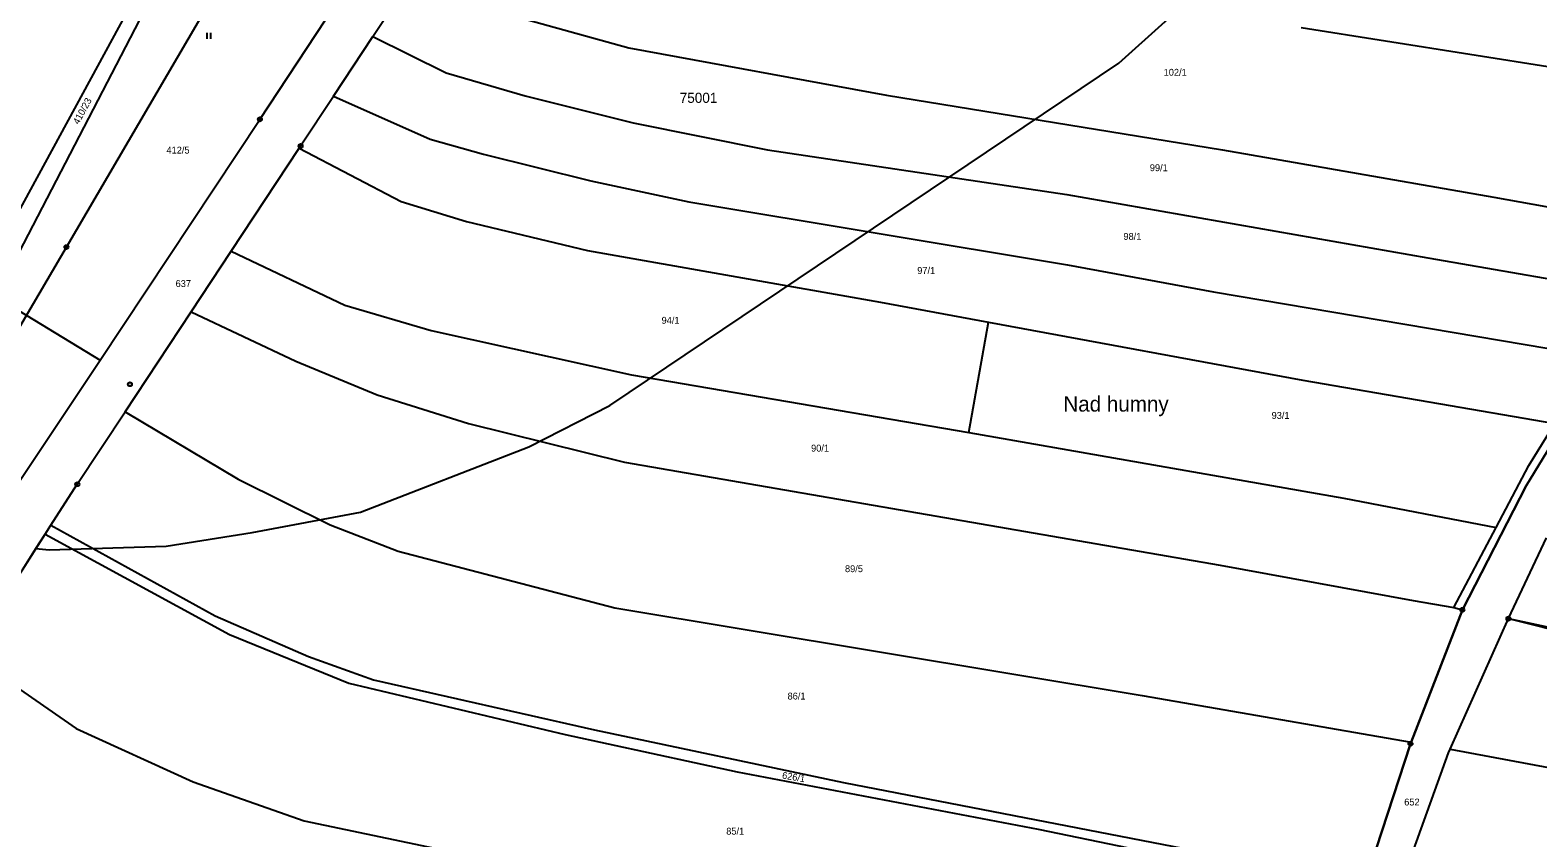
# Model space of a CAD drawing. Extents: x -743888 to -742027, y -1128394 to -1126768.
# Drawn here: x -743633.6 to -743261.6, y -1127319.9 to -1127120.7 of the extents above; entities that cross this region are included whole.
import ezdxf

# ---------------------------------------------------------------- set-up
doc = ezdxf.new("R2010")
doc.units = 0
for name, color, linetype in [('Vrstva 1', 7, 'Continuous'), ('Vrstva 12', 7, 'Continuous'), ('Vrstva 15', 7, 'Continuous'), ('Vrstva 18', 7, 'Continuous'), ('Vrstva 24', 7, 'Continuous'), ('Vrstva 25', 7, 'Continuous'), ('Vrstva 26', 7, 'Continuous'), ('Vrstva 52', 7, 'Continuous'), ('Vrstva 53', 7, 'Continuous'), ('Vrstva 6', 7, 'Continuous')]:
    doc.layers.add(name, color=color, linetype=linetype)

msp = doc.modelspace()

# ---------------------------------------------------------------- linework, layer by layer
at = {"layer": 'Vrstva 1'}
for points in [[(-743642.12, -1127186.45), (-743597.45, -1127100.54)], [(-743549.04, -1127122.29), (-743538.97, -1127107.07)], [(-743576.94, -1127142.72), (-743560.72, -1127118.19)], [(-743558.76, -1127136.98), (-743549.04, -1127122.29)], [(-743566.89, -1127149.27), (-743558.76, -1127136.98)], [(-743616.38, -1127202.08), (-743576.94, -1127142.72)], [(-743567.27, -1127149.84), (-743566.89, -1127149.27)], [(-743584.02, -1127175.2), (-743567.27, -1127149.84)], [(-743593.92, -1127190.2), (-743584.02, -1127175.2)], [(-743610.18, -1127214.83), (-743593.92, -1127190.2)], [(-743636.37, -1127232.18), (-743616.38, -1127202.08)], [(-743264.54, -1127233.06), (-743246.95, -1127204.21)], [(-743621.98, -1127232.71), (-743610.18, -1127214.83)], [(-743263.84, -1127228.1), (-743257.45, -1127217.75)], [(-743271.94, -1127243.4), (-743263.84, -1127228.1)], [(-743628.48, -1127242.82), (-743621.98, -1127232.71)], [(-743280.26, -1127263.68), (-743264.54, -1127233.06)], [(-743635.53, -1127253.78), (-743629.87, -1127244.98)], [(-743629.87, -1127244.98), (-743628.48, -1127242.82)], [(-743282.34, -1127263.07), (-743271.94, -1127243.4)], [(-743268.91, -1127265.85), (-743259.48, -1127245.93)], [(-743292.92, -1127296.34), (-743280.26, -1127263.68)], [(-743282.34, -1127263.07), (-743280.26, -1127263.68)], [(-743283.26, -1127298.02), (-743268.91, -1127265.85)], [(-743268.91, -1127265.85), (-743201.41, -1127282.77)], [(-743304.3, -1127331.19), (-743293.07, -1127296.72)], [(-743293.07, -1127296.72), (-743292.92, -1127296.34)], [(-743283.68, -1127298.96), (-743283.26, -1127298.02)], [(-743294.99, -1127330.28), (-743283.68, -1127298.96)]]:
    msp.add_lwpolyline(points, dxfattribs=at)
at = {"layer": 'Vrstva 12'}
for points in [[(-743624.66, -1127174.21), (-743579.34, -1127096.74)], [(-743666.59, -1127245.69), (-743624.66, -1127174.21)]]:
    msp.add_lwpolyline(points, dxfattribs=at)
at = {"layer": 'Vrstva 24'}
for p, q in [((-743576.99, -1127142.72), (-743576.89, -1127142.72)), ((-743566.94, -1127149.27), (-743566.84, -1127149.27)), ((-743609.04, -1127208.06), (-743608.94, -1127208.06)), ((-743622.03, -1127232.71), (-743621.93, -1127232.71)), ((-743280.31, -1127263.68), (-743280.21, -1127263.68)), ((-743268.96, -1127265.85), (-743268.86, -1127265.85)), ((-743293.12, -1127296.72), (-743293.02, -1127296.72))]:
    msp.add_line(p, q, dxfattribs=at)
for centre in [(-743576.94, -1127142.72), (-743566.89, -1127149.27), (-743608.99, -1127208.06), (-743621.98, -1127232.71), (-743280.26, -1127263.68), (-743268.91, -1127265.85), (-743293.07, -1127296.72)]:
    msp.add_circle(centre, 0.499, dxfattribs=at)
at = {"layer": 'Vrstva 25'}
for p, q in [((-743590.03, -1127121.4), (-743590.03, -1127122.9)), ((-743589.03, -1127122.9), (-743589.03, -1127121.4))]:
    msp.add_line(p, q, dxfattribs=at)
at = {"layer": 'Vrstva 26'}
for p, q in [((-743625.12, -1127174.39), (-743624.47, -1127173.75)), ((-743624.86, -1127174.66), (-743624.21, -1127174.01))]:
    msp.add_line(p, q, dxfattribs=at)
msp.add_circle((-743624.66, -1127174.21), 0.5, dxfattribs=at)
at = {"layer": 'Vrstva 52'}
for points in [[(-743677.39, -1127227.76), (-743671.64, -1127230.23), (-743666.12, -1127232.6), (-743642.12, -1127186.45), (-743597.45, -1127100.54), (-743561.27, -1127030.96), (-743560.68, -1127029.82), (-743555.91, -1127020.65)], [(-743646.21, -1127246.53), (-743643.98, -1127243.27), (-743636.37, -1127232.18), (-743616.38, -1127202.08), (-743576.94, -1127142.72), (-743560.72, -1127118.19), (-743522.03, -1127059.68), (-743516.89, -1127051.64), (-743512.05, -1127044.08)], [(-743632.18, -1127248.58), (-743629.87, -1127244.98), (-743628.48, -1127242.82), (-743621.98, -1127232.71), (-743610.18, -1127214.83), (-743593.92, -1127190.2), (-743584.02, -1127175.2), (-743567.27, -1127149.84), (-743566.89, -1127149.27), (-743558.76, -1127136.98), (-743549.04, -1127122.29), (-743538.97, -1127107.07), (-743518.91, -1127076.75), (-743511.71, -1127065.87), (-743507.61, -1127059.97), (-743505.37, -1127056.75), (-743500.91, -1127053.2), (-743495.43, -1127050.9), (-743489.52, -1127050.44), (-743483.7, -1127051.01), (-743385.04, -1127067.93), (-743357.57, -1127072.68)], [(-743632.18, -1127248.58), (-743628.94, -1127248.88), (-743600.06, -1127248), (-743578.88, -1127244.63), (-743552.13, -1127239.63), (-743510.56, -1127223.5), (-743490.63, -1127213.25), (-743365.06, -1127128.88), (-743353.56, -1127118.63), (-743348.06, -1127111), (-743345.5, -1127108.5), (-743344.25, -1127106), (-743343, -1127100.88), (-743343.38, -1127088.13), (-743345.5, -1127082.13), (-743351.06, -1127075), (-743357.57, -1127072.68)], [(-743246.95, -1127204.21), (-743264.54, -1127233.06), (-743280.26, -1127263.68), (-743292.92, -1127296.34), (-743293.07, -1127296.72), (-743304.3, -1127331.19)], [(-743294.99, -1127330.28), (-743283.68, -1127298.96), (-743283.26, -1127298.02), (-743268.91, -1127265.85), (-743259.48, -1127245.93)], [(-743678.44, -1127390.67), (-743671.53, -1127378.48), (-743658.11, -1127354.78), (-743660.69, -1127352.59), (-743659, -1127349), (-743658.7, -1127346.57), (-743664.22, -1127341.91), (-743673.62, -1127333.98), (-743679.84, -1127327.83), (-743680.26, -1127326.97), (-743682.93, -1127324.62), (-743682.05, -1127323.29), (-743681.13, -1127321.96), (-743677.33, -1127316.28), (-743672.05, -1127308.38), (-743649.24, -1127274.28), (-743635.53, -1127253.78), (-743632.18, -1127248.58)]]:
    msp.add_lwpolyline(points, dxfattribs=at)
at = {"layer": 'Vrstva 6'}
for points in [[(-743646.48, -1127183.8), (-743600.41, -1127099.12)], [(-743521.87, -1127115.17), (-743485.93, -1127125.07)], [(-743549.04, -1127122.29), (-743530.98, -1127131.21)], [(-743320.04, -1127120.06), (-743257.58, -1127129.9)], [(-743485.93, -1127125.07), (-743422.36, -1127136.74)], [(-743530.98, -1127131.21), (-743511.45, -1127136.91)], [(-743558.76, -1127136.98), (-743534.96, -1127147.61)], [(-743511.45, -1127136.91), (-743484.81, -1127143.57)], [(-743422.36, -1127136.74), (-743339.46, -1127150.28)], [(-743484.81, -1127143.57), (-743451.69, -1127150.21)], [(-743534.96, -1127147.61), (-743521.74, -1127151.29)], [(-743567.27, -1127149.84), (-743542.08, -1127162.94)], [(-743521.74, -1127151.29), (-743495.31, -1127157.9)], [(-743451.69, -1127150.21), (-743377.84, -1127161.22)], [(-743339.46, -1127150.28), (-743272.53, -1127161.95)], [(-743495.31, -1127157.9), (-743471.09, -1127163.04)], [(-743542.08, -1127162.94), (-743525.94, -1127167.89)], [(-743471.09, -1127163.04), (-743377.67, -1127178.61)], [(-743377.84, -1127161.22), (-743288.76, -1127176.89)], [(-743272.53, -1127161.95), (-743227.63, -1127169.97)], [(-743525.94, -1127167.89), (-743496.12, -1127175.06)], [(-743584.02, -1127175.2), (-743556, -1127188.55)], [(-743496.12, -1127175.06), (-743423.8, -1127187.83)], [(-743377.67, -1127178.61), (-743341.69, -1127185.22)], [(-743288.76, -1127176.89), (-743237.55, -1127185.73)], [(-743642.12, -1127186.45), (-743616.38, -1127202.08)], [(-743341.69, -1127185.22), (-743247.25, -1127201.23)], [(-743593.92, -1127190.2), (-743568.07, -1127202.32)], [(-743556, -1127188.55), (-743534.64, -1127194.81)], [(-743423.8, -1127187.83), (-743397.19, -1127192.74)], [(-743402, -1127219.97), (-743397.19, -1127192.74)], [(-743397.19, -1127192.74), (-743319.64, -1127207.06)], [(-743534.64, -1127194.81), (-743485.26, -1127205.7)], [(-743568.07, -1127202.32), (-743548.02, -1127210.66)], [(-743485.26, -1127205.7), (-743402, -1127219.97)], [(-743319.64, -1127207.06), (-743257.45, -1127217.75)], [(-743548.02, -1127210.66), (-743525.49, -1127217.7)], [(-743610.18, -1127214.83), (-743582.27, -1127231.48)], [(-743525.49, -1127217.7), (-743486.97, -1127227.24)], [(-743402, -1127219.97), (-743309.52, -1127236.1)], [(-743486.97, -1127227.24), (-743340.01, -1127252.63)], [(-743582.27, -1127231.48), (-743559.61, -1127242.69)], [(-743309.52, -1127236.1), (-743271.94, -1127243.4)], [(-743629.87, -1127244.98), (-743584.41, -1127269.73)], [(-743628.48, -1127242.82), (-743587.96, -1127265.17)], [(-743559.61, -1127242.69), (-743542.82, -1127249.21)], [(-743542.82, -1127249.21), (-743489.36, -1127263.15)], [(-743340.01, -1127252.63), (-743292.44, -1127261.41)], [(-743489.36, -1127263.15), (-743359.24, -1127284.78)], [(-743292.44, -1127261.41), (-743282.34, -1127263.07)], [(-743587.96, -1127265.17), (-743564.92, -1127275.2)], [(-743268.91, -1127265.85), (-743211.37, -1127278.18)], [(-743584.41, -1127269.73), (-743555, -1127281.78)], [(-743649.24, -1127274.28), (-743622.26, -1127292.92)], [(-743564.92, -1127275.2), (-743548.91, -1127280.9)], [(-743555, -1127281.78), (-743501.66, -1127294.44)], [(-743548.91, -1127280.9), (-743494.35, -1127293.28)], [(-743359.24, -1127284.78), (-743292.92, -1127296.34)], [(-743622.26, -1127292.92), (-743593.43, -1127306.05)], [(-743494.35, -1127293.28), (-743432.95, -1127306.22)], [(-743501.66, -1127294.44), (-743459.15, -1127303.62)], [(-743283.26, -1127298.02), (-743244.44, -1127305.3)], [(-743459.15, -1127303.62), (-743384.95, -1127317.8)], [(-743593.43, -1127306.05), (-743565.99, -1127315.69)], [(-743432.95, -1127306.22), (-743304.3, -1127331.19)], [(-743565.99, -1127315.69), (-743506.37, -1127328.2)], [(-743384.95, -1127317.8), (-743340.32, -1127326.98)]]:
    msp.add_lwpolyline(points, dxfattribs=at)

# ---------------------------------------------------------------- texts
at = {"layer": 'Vrstva 15'}
msp.add_text('Nad humny', height=3.8, dxfattribs=at).set_placement((-743378.71, -1127214.79))
at = {"layer": 'Vrstva 18'}
for s, p in [('102/1', (-743353.96, -1127131.97)), ('412/5', (-743599.98, -1127151.16)), ('99/1', (-743357.37, -1127155.5)), ('98/1', (-743363.89, -1127172.43)), ('97/1', (-743414.76, -1127180.85)), ('637', (-743597.73, -1127184.07)), ('94/1', (-743477.83, -1127193.13)), ('93/1', (-743327.33, -1127216.58)), ('90/1', (-743440.95, -1127224.65)), ('89/5', (-743432.58, -1127254.38)), ('86/1', (-743446.75, -1127285.79)), ('652', (-743294.61, -1127311.92)), ('85/1', (-743461.88, -1127319.11))]:
    msp.add_text(s, height=1.7, dxfattribs=at).set_placement(p)
for s, rotation, p in [('410/23', 61.564, (-743621.66, -1127144.12)), ('626/1', 350.3902, (-743448.19, -1127305.25))]:
    msp.add_text(s, height=1.7, rotation=rotation, dxfattribs=at).set_placement(p)
at = {"layer": 'Vrstva 53'}
msp.add_text('75001', height=2.5, dxfattribs=at).set_placement((-743473.36, -1127138.66))

doc.saveas('drawing.dxf')
